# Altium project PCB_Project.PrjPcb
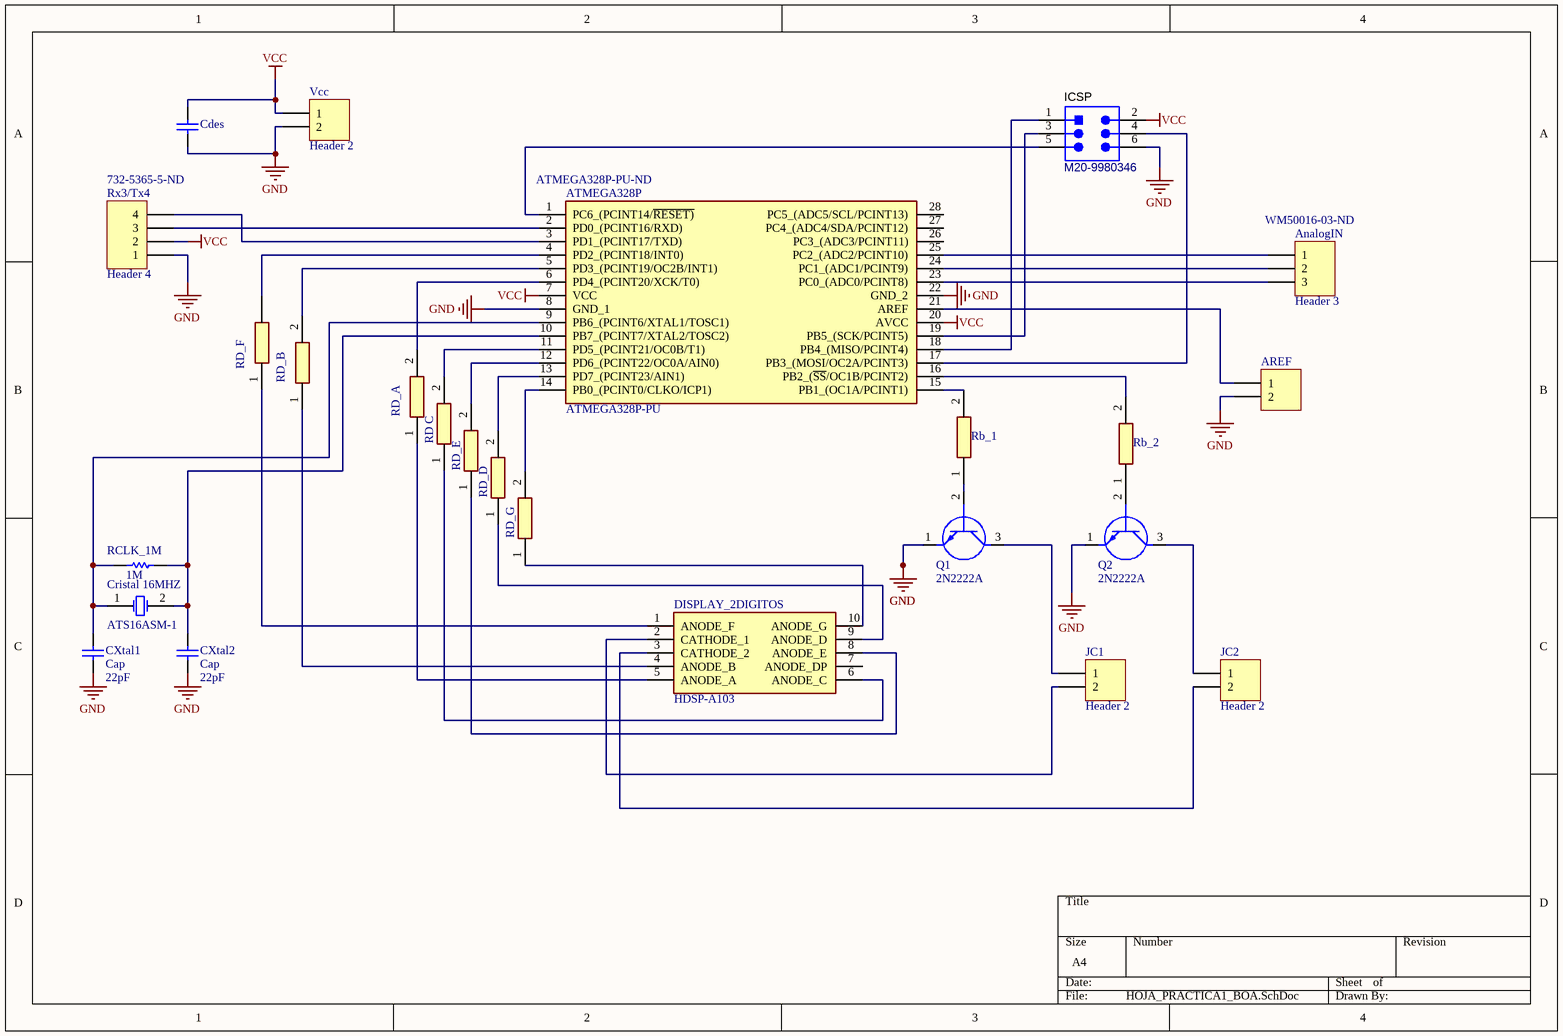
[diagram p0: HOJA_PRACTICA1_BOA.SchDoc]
1 sheet, 25 parts. Net scope: global (net labels, ports and power ports of the same name join across sheets).
Board file: PCB_PRACTICA1_BOA.PcbDoc

## Sheet HOJA_PRACTICA1_BOA.SchDoc
size A4

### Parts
AnalogIN  Header 3  Supplier Part Number 1: WM50016-03-ND  [HDR1X3]
AREF  VCC  [HDR1X2]  (value not drawn)
ATMEGA328P  ATMEGA328P-PU  Supplier Part Number 1: ATMEGA328P-PU-ND  [DIP794W53P254L3467H457Q28N]
Cdes  CGA3E3X7S2A104K080AB  [CAPC1608X90X20ML10]  (value not drawn)
Cristal_16MHZ  ATS16ASM-1  [CTS-ATS-SM-XTAL-2]
CXtal1  Cap  value 22pF  [C0805]
CXtal2  Cap  value 22pF  [C0805]
DISPLAY_2DIGITOS  HDSP-A103  [DIP508W51P254L1270H609Q10N]
ICSP  M20-9980346  [HRWN-M20-9980346_V]
JC1  Header 2  [HDR1X2]
JC2  Header 2  [HDR1X2]
Q1  2N2222A  [TO-18_4]
Q2  2N2222A  [TO-18_4]
Rb_1  CR1206-FX-2200ELF  [RESC3216X75N]  (value not drawn)
Rb_2  CR1206-FX-2200ELF  [RESC3216X75N]  (value not drawn)
RCLK_1M  value 1M  [C1206]  (hidden comment: Res1)
RD_A  CR1206-FX-2200ELF  [RESC3216X75N]  (value not drawn)
RD_B  CR1206-FX-2200ELF  [RESC3216X75N]  (value not drawn)
RD_C  CR1206-FX-2200ELF  [RESC3216X75N]  (value not drawn)
RD_D  CR1206-FX-2200ELF  [RESC3216X75N]  (value not drawn)
RD_E  CR1206-FX-2200ELF  [RESC3216X75N]  (value not drawn)
RD_F  CR1206-FX-2200ELF  [RESC3216X75N]  (value not drawn)
RD_G  CR1206-FX-2200ELF  [RESC3216X75N]  (value not drawn)
Rx3/Tx4  Header 4  Supplier Part Number 1: 732-5365-5-ND  [HDR1X4]
Vcc  Header 2  [HDR1X2]

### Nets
GND: AREF.2 ATMEGA328P.8(GND_1) ATMEGA328P.22(GND_2) Cdes.1 CXtal1.1 CXtal2.1 ICSP.6 Q1.1(E) Q2.1(E) Rx3/Tx4.1 Vcc.2
VCC: ATMEGA328P.7(VCC) ATMEGA328P.20(AVCC) Cdes.2 ICSP.2 Rx3/Tx4.2 Vcc.1
NetAnalogIN_1: AnalogIN.1 ATMEGA328P.25(PC2_(ADC2/PCINT10))
NetAnalogIN_2: AnalogIN.2 ATMEGA328P.24(PC1_(ADC1/PCINT9))
NetAnalogIN_3: AnalogIN.3 ATMEGA328P.23(PC0_(ADC0/PCINT8))
NetAREF_1: AREF.1 ATMEGA328P.21(AREF)
NetATMEGA328P_1: ATMEGA328P.1(PC6_(PCINT14/~{RESET)}) ICSP.5
NetATMEGA328P_2: ATMEGA328P.2(PD0_(PCINT16/RXD)) Rx3/Tx4.3
NetATMEGA328P_3: ATMEGA328P.3(PD1_(PCINT17/TXD)) Rx3/Tx4.4
NetATMEGA328P_4: ATMEGA328P.4(PD2_(PCINT18/INT0)) RD_F.2
NetATMEGA328P_5: ATMEGA328P.5(PD3_(PCINT19/OC2B/INT1)) RD_B.2
NetATMEGA328P_6: ATMEGA328P.6(PD4_(PCINT20/XCK/T0)) RD_A.2
NetATMEGA328P_9: ATMEGA328P.9(PB6_(PCINT6/XTAL1/TOSC1)) Cristal_16MHZ.1(X1) CXtal1.2 RCLK_1M.2
NetATMEGA328P_10: ATMEGA328P.10(PB7_(PCINT7/XTAL2/TOSC2)) Cristal_16MHZ.2(X2) CXtal2.2 RCLK_1M.1
NetATMEGA328P_11: ATMEGA328P.11(PD5_(PCINT21/OC0B/T1)) RD_C.2
NetATMEGA328P_12: ATMEGA328P.12(PD6_(PCINT22/OC0A/AIN0)) RD_E.2
NetATMEGA328P_13: ATMEGA328P.13(PD7_(PCINT23/AIN1)) RD_D.2
NetATMEGA328P_14: ATMEGA328P.14(PB0_(PCINT0/CLKO/ICP1)) RD_G.2
NetATMEGA328P_15: ATMEGA328P.15(PB1_(OC1A/PCINT1)) Rb_1.2
NetATMEGA328P_16: ATMEGA328P.16(PB2_(~{SS}/OC1B/PCINT2)) Rb_2.2
NetATMEGA328P_17: ATMEGA328P.17(PB3_(MOSI/OC2A/PCINT3)) ICSP.4
NetATMEGA328P_18: ATMEGA328P.18(PB4_(MISO/PCINT4)) ICSP.1
NetATMEGA328P_19: ATMEGA328P.19(PB5_(SCK/PCINT5)) ICSP.3
NetDISPLAY_2DIGITOS_1: DISPLAY_2DIGITOS.1(ANODE_F) RD_F.1
NetDISPLAY_2DIGITOS_2: DISPLAY_2DIGITOS.2(CATHODE_1) JC1.2
NetDISPLAY_2DIGITOS_3: DISPLAY_2DIGITOS.3(CATHODE_2) JC2.2
NetDISPLAY_2DIGITOS_4: DISPLAY_2DIGITOS.4(ANODE_B) RD_B.1
NetDISPLAY_2DIGITOS_5: DISPLAY_2DIGITOS.5(ANODE_A) RD_A.1
NetDISPLAY_2DIGITOS_6: DISPLAY_2DIGITOS.6(ANODE_C) RD_C.1
NetDISPLAY_2DIGITOS_8: DISPLAY_2DIGITOS.8(ANODE_E) RD_E.1
NetDISPLAY_2DIGITOS_9: DISPLAY_2DIGITOS.9(ANODE_D) RD_D.1
NetDISPLAY_2DIGITOS_10: DISPLAY_2DIGITOS.10(ANODE_G) RD_G.1
NetJC1_1: JC1.1 Q1.3(C)
NetJC2_1: JC2.1 Q2.3(C)
NetQ1_2: Q1.2(B) Rb_1.1
NetQ2_2: Q2.2(B) Rb_2.1

Not connected (* = marked no-connect by the designer): ATMEGA328P 26(PC3_(ADC3/PCINT11)) 27(PC4_(ADC4/SDA/PCINT12)) 28(PC5_(ADC5/SCL/PCINT13)); DISPLAY_2DIGITOS 7(ANODE_DP)

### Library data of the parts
AnalogIN = Header 3: Header, 3-Pin
AREF JC1 JC2 Vcc = Header 2: Header, 2-Pin
ATMEGA328P = ATMEGA328P-PU: Integrated Circuit; Manufacturer_Name: Microchip; Allied_Number: 70332157
Cdes = CMP-2000-04983-1: Chip Capacitor, 100 nF, +/- 10%, 100 V, -55 to 125 degC, 0603 (1608 Metric), RoHS, Tape and Reel; PCN Part Number: MLCCPartNumberChange30/Nov/2012; Manufacturer: TDK; Capacitance: 0.1µF; Kits: 445-9007-KIT-ND-KITCAPCERAUTO100V-600VSMD445-9006-KIT-ND-KITCAPCERAUTO100V-630VSMDSAMPLEKIT1006-ND-KITCAPCERAUTO100V-630V; Online Catalog: CGASeries,AutomotiveGeneral,MidandHighVoltage; Voltage - Rated: 100V; Product Training Modules: CGASeriesforAutomotiveApplicationsSEAT,CCV,andTVCLDesignToolsGuidetoReplacinganElectrolyticCapacitorwithanMLCC; Featured Product: CGASeriesMLCCCapacitors; Other Names: 445-6938-1; Temperature Coefficient: X7S
Cristal_16MHZ = CMP-0585-00002-2: ATS-SM Series Quartz Crystal, 16 MHz, -20 to 70 degC, 11.1 x 4.83 x 4.3mm SMD, RoHS, Tape and Reel; Manufacturer: CTS Corporation; Shunt Capacitance (C0): 7.0 pF Max; Frequency: 16 MHz; Oscillation Mode: Fundamental or 3rd Overtone; Crystal Cut: AT-Cut; ESR Maximum: 40 Ohms; Drive Level (Type): 100 uW
CXtal1 CXtal2 = Cap: Capacitor
DISPLAY_2DIGITOS = HDSP-A103: Display; Manufacturer_Name: Avago Technologies
ICSP = CMP-2000-06636-1: Male Header, Pitch 2.54 mm, 2 x 3 Position, Height 8.64 mm, Tail Length 3 mm, -40 to 105 degC, RoHS, Bulk; Manufacturer: Harwin-Inc.; Row Spacing: 0.100"(2.54mm); Connector Type: Header,Unshrouded,Breakaway; Number of Positions Loaded: All; Number of Positions: 6
Q1 Q2 = 2N2222A: Transistor BJT NPN; Manufacturer_Name: Microsemi Corporation
Rb_1 Rb_2 RD_A RD_B RD_C RD_D RD_E RD_F RD_G = CR1206-FX-2200ELF: Resistor; Manufacturer_Name: Bourns; Allied_Number: 70155093
RCLK_1M = Res1: Resistor
Rx3/Tx4 = Header 4: Header, 4-Pin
